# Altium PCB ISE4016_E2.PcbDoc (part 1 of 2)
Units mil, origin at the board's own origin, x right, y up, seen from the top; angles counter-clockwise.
Board outline 5600 x 2000 mil, 4 copper layers (Top Layer, InternalPlane1, MidLayer2, Bottom Layer), stack 59 mil thick; 110 components, 63 nets, 365 pads, 250 vias.
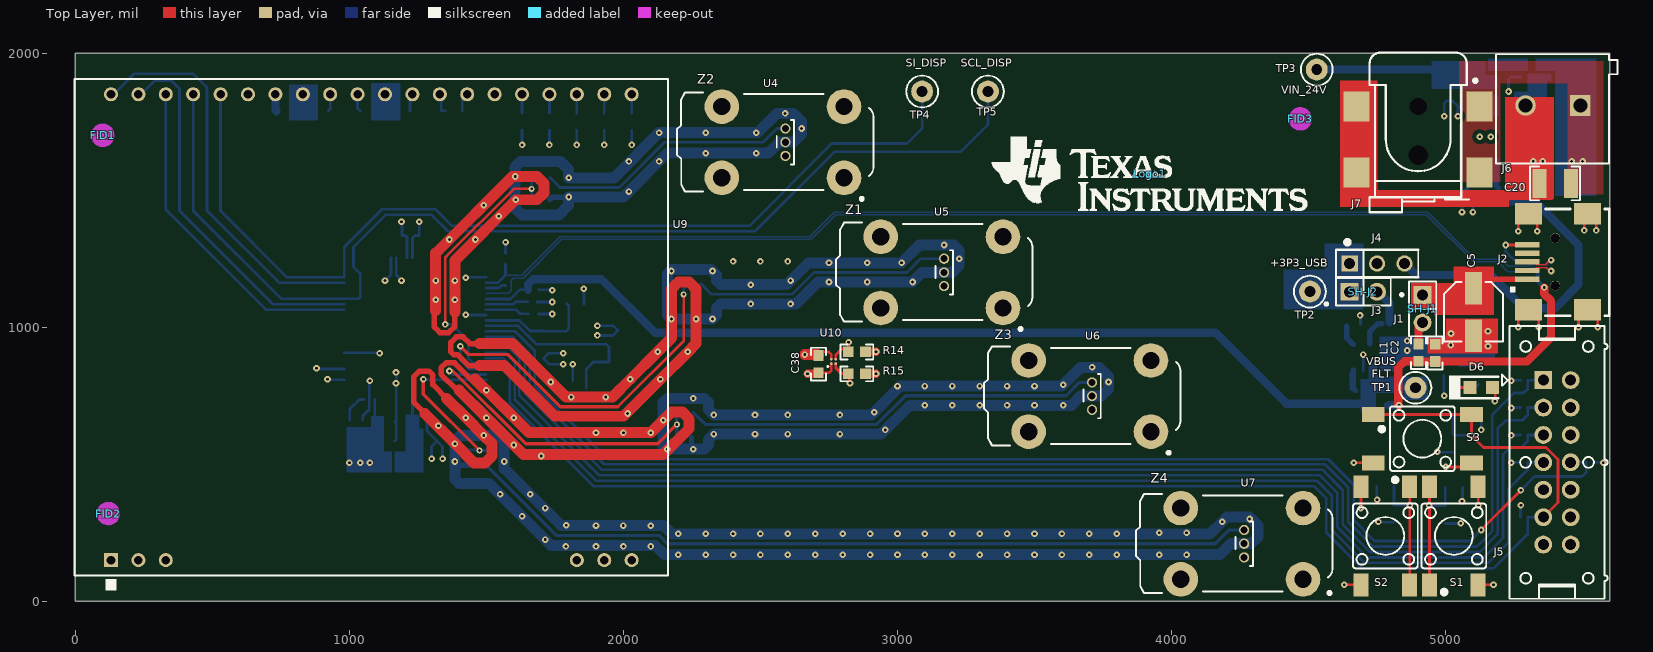
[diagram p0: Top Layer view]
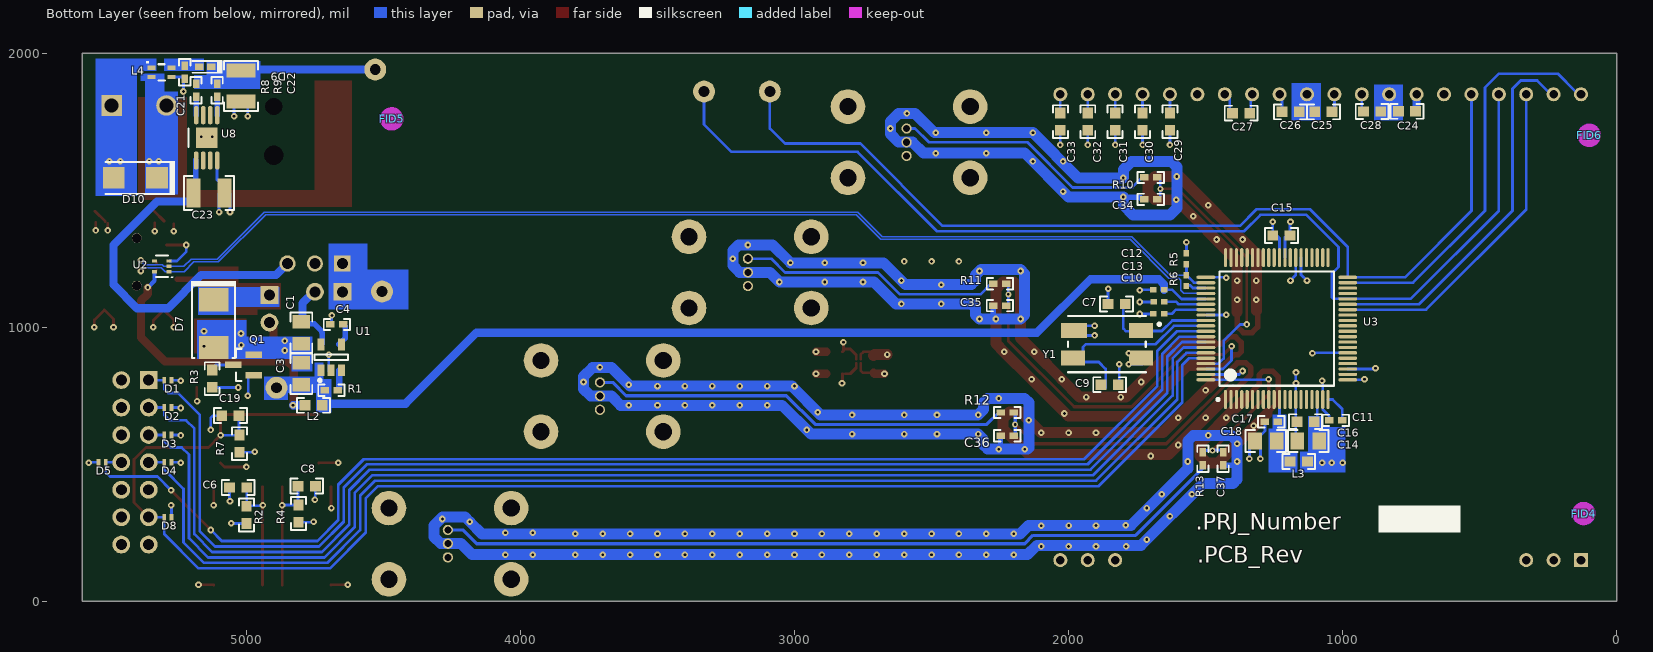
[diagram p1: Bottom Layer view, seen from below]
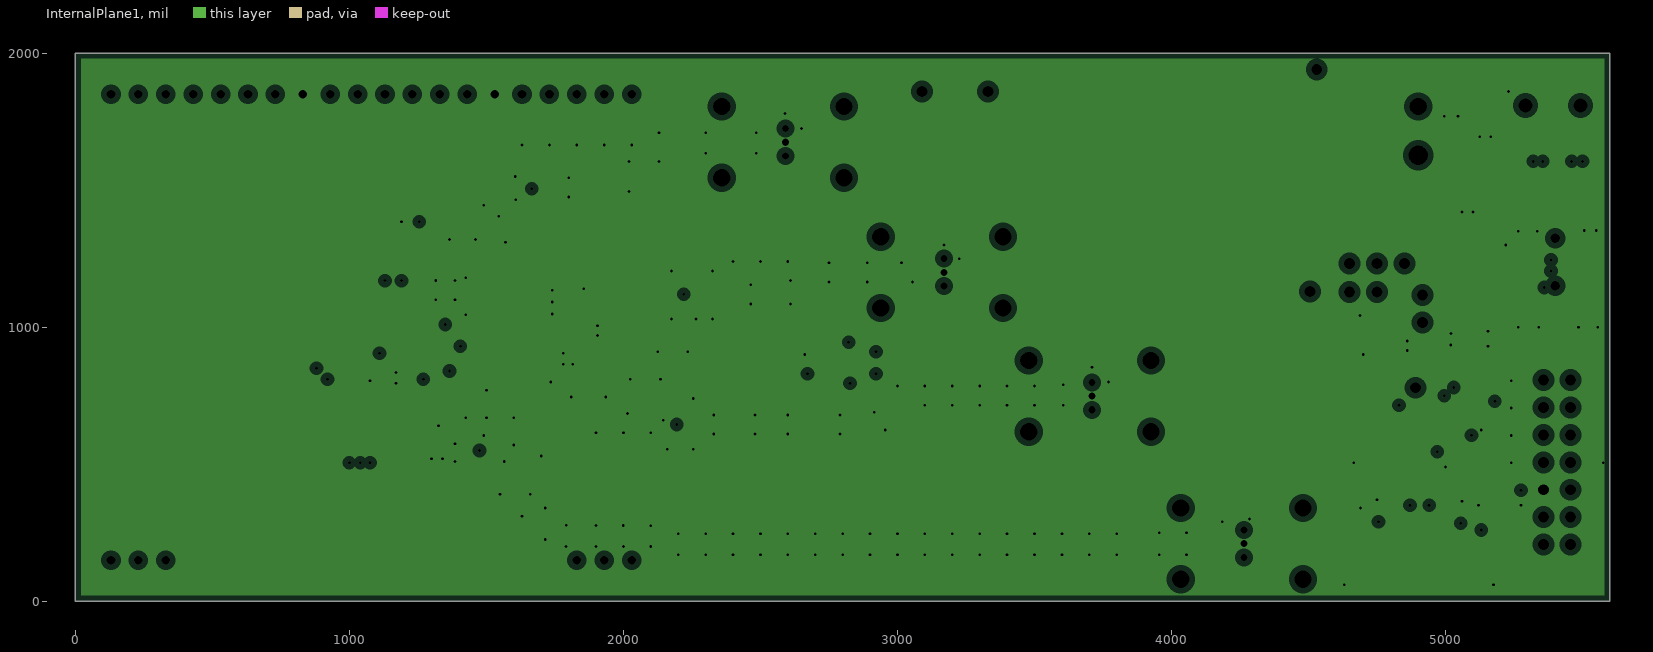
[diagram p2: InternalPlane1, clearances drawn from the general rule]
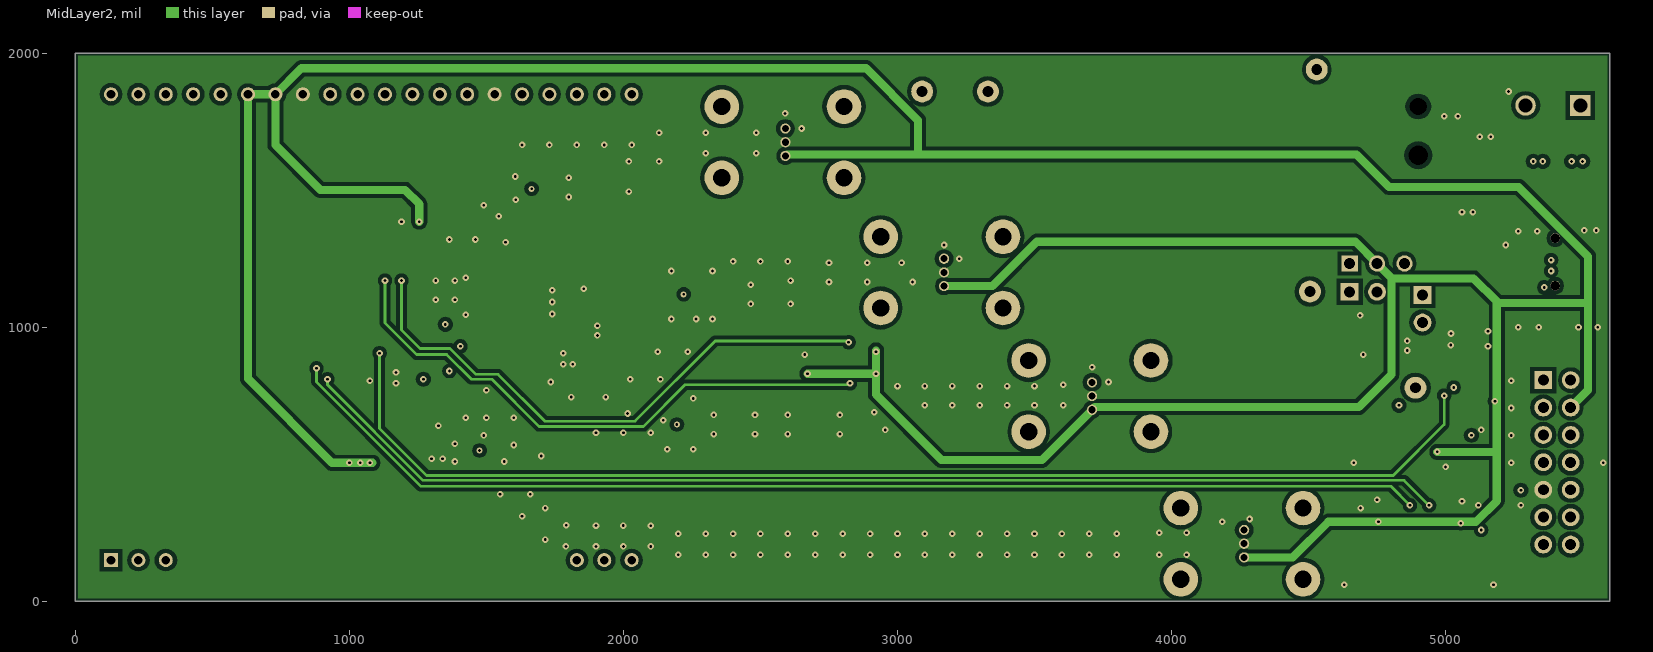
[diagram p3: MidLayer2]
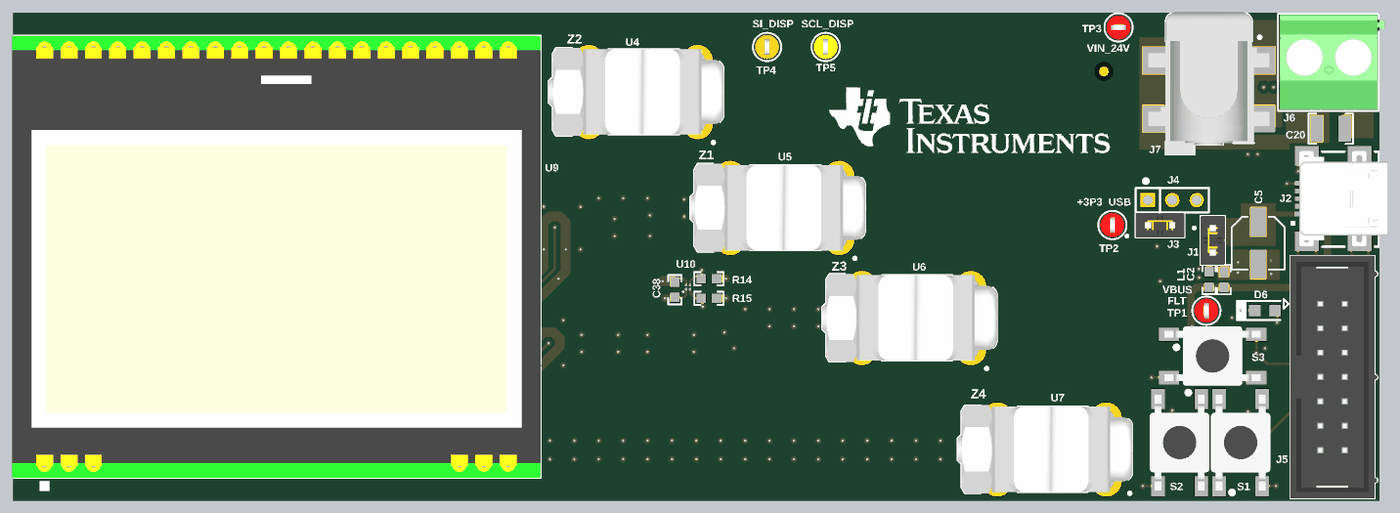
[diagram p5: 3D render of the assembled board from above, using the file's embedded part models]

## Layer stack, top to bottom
Top Layer: signal copper 1.4
Dielectric: prepreg 5.2, 370 HR, Dk 4.8
InternalPlane1: plane copper 1.4, net GND
Dielectric: core 43, 370 HR, Dk 4.8
MidLayer2: signal copper 1.4
Dielectric: prepreg 5.2, 370 HR, Dk 4.8
Bottom Layer: signal copper 1.4

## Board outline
0,0 5600,0 5600,2000 0,2000

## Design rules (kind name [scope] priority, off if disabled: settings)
AcuteAngle [All] p1: minimum=4.50000000000000E+0001 checktracksonly=FALSE
AssemblyTestPointUsage [All] p1: valid=2
Clearance Clearance_BoardEdge_MountingHoles [OnCopper and InComponentClass('Mounting Holes') vs IsKeepOut] p1: gap=40
Clearance Clearance_BoardEdge_Poly [OnCopper and InPoly vs IsKeepOut] p2: gap=25
Clearance Clearance_BoardEdge [OnCopper and Not InComponentClass('Logo') and not InComponentClass('FiducialMark') and not InRegion(1000,500,4000,800) and Not IsKeepout vs IsKeepOut] p3: gap=75
Clearance Clearance_Poly [InPolygon] p4: gap=15
Clearance [All] p5: gap=5
ComponentClearance ComponentClearance_Logo [InComponentClass('Logo')] p1 off: gap=50 collisioncheckmode=3 verticalgap=10 showdistances=FALSE
ComponentClearance ComponentClearance_ScrewToNut [(HasFootprint('NY PMS 440 0025 PH')) vs (HasFootprint('Keystone_1902C'))] p2: gap=5 collisioncheckmode=3 verticalgap=10 showdistances=FALSE
ComponentClearance ComponentClearance_MountingHoles [InComponentClass('Mounting Holes')] p3 off: gap=250 collisioncheckmode=3 verticalgap=100000 showdistances=FALSE
ComponentClearance ComponentClearance_SmallPassives [HasFootprint('0201*') or HasFootprint('0402*') or HasFootprint('0508') or HasFootprint('0603*') or HasFootprint('0612') or HasFootprint('0805*') or HasFootprint('0815*') or HasFootprint('0830*') or HasFootprint('1206*') or HasFootprint('1210*') or HasFootprint('1808*') or HasFootprint('1812*') or HasFootprint('1825*') or HasFootprint('2010*') or HasFootprint('2220*') or HasFootprint('2225*') or HasFootprint('2512*') or HasFootprint('2728*') or HasFootprint('3518*') vs HasFootprint('0201*') or HasFootprint('0402*') or HasFootprint('0508') or HasFootprint('0603*') or HasFootprint('0612') or HasFootprint('0805*') or HasFootprint('0815*') or HasFootprint('0830*') or HasFootprint('1206*') or HasFootprint('1210*') or HasFootprint('1808*') or HasFootprint('1812*') or HasFootprint('1825*') or HasFootprint('2010*') or HasFootprint('2220*') or HasFootprint('2225*') or HasFootprint('2512*') or HasFootprint('2728*') or HasFootprint('3518*')] p4: gap=20 collisioncheckmode=3 verticalgap=10 showdistances=FALSE
ComponentClearance ComponentClearance_THtoSMT [IsThruComponent vs IsSMTComponent] p5 off: gap=100 collisioncheckmode=3 verticalgap=30 showdistances=FALSE
ComponentClearance ComponentClearance_THtoTH [IsThruComponent vs IsThruComponent] p6 off: gap=118.11 collisioncheckmode=3 verticalgap=30 showdistances=FALSE
ComponentClearance [All] p7 off: gap=10 collisioncheckmode=3 verticalgap=10 showdistances=FALSE
DiffPairsRouting [All] p1: maxlimit=100 minlimit=5 mostfreqgap=5 maxuncoupledlength=4000
FabricationTestPointUsage TestPointUsage [All] p1: valid=2 allowmultiple=FALSE
FabricationTestpoint Testpoint [All] p1: side=3 testpointundercomponent=TRUE minsize=40 maxsize=100 preferedsize=60 minholesize=0 maxholesize=40 preferedholesize=32 testpointgrid=1 allowsidetop=TRUE allowsidebottom=TRUE usegrid=TRUE gridtolerance=0.01
FanoutControl Fanout_LCC [IsLCC] p1: bgadir=Out bgaviamode=Centered fanoutstyle=Auto fanoutdirection=Alternating viagrid=1 // Fanout_LCC (Default Rule)
FanoutControl Fanout_BGA [IsBGA] p2: bgadir=Out bgaviamode=Centered fanoutstyle=Auto fanoutdirection=Alternating viagrid=1 // Fanout_BGA (Default Rule)
FanoutControl Fanout_Default [All] p4: bgadir=Out bgaviamode=Centered fanoutstyle=Auto fanoutdirection=Alternating viagrid=1 // Fanout_Default (Default Rule)
FanoutControl Fanout_Small [(CompPinCount < 5)] p5: bgadir=Out bgaviamode=Centered fanoutstyle=Auto fanoutdirection=OutThenIn viagrid=1 // Fanout_Small (Default Rule)
Height [All] p1: minheight=0 maxheight=4000 prefheight=500
HoleSize [All] p1: absolutevalues=TRUE maxlimit=251 minlimit=8 maxpercent=80.000 minpercent=20.000
MinimumAnnularRing [All] p1: minimumring=5
MinimumSolderMaskSliver MinimumSolderMaskSliver_Logo [InComponentClass('Logo') vs InComponentClass('Logo')] p1: minsoldermaskwidth=0.7
MinimumSolderMaskSliver [All] p2: minsoldermaskwidth=1
PlaneClearance [All] p1: clearance=20
PlaneConnect [All] p1: planeconnectstyle=Relief reliefexpansion=10 reliefentries=4 reliefconductorwidth=10 reliefairgap=10
PolygonConnect [All] p1: connectstyle=Direct reliefconductorwidth=10 reliefentries=4 polygonreliefangle="90 Angle" airgapwidth=10
RoutingVias [All] p1: holewidth=16 width=34 viastyle="Through Hole" minholewidth=8 minwidth=20 maxholewidth=40 maxwidth=65
SMDToCorner [All] p1: distance=30000
SilkToSilkClearance [All] p1: silktosilkclearance=5
SilkscreenOverComponentPads [All] p1: minsilkscreentomaskgap=5
SolderMaskExpansion [All] p1: expansion=3
Width "Schematic Width Constraint_6" [InNet('NetC20_1')] p1: maxlimit=80 minlimit=80 preferedwidth=80
Width "Schematic Width Constraint_5" [InNet('+3P3_USB')] p2: maxlimit=100 minlimit=5 preferedwidth=25
Width "Schematic Width Constraint_4" [InNet('VBUS_FLT')] p3: maxlimit=100 minlimit=5 preferedwidth=25
Width "Schematic Width Constraint_3" [InNet('+3P3V_OUT')] p4: maxlimit=100 minlimit=5 preferedwidth=25
Width "Schematic Width Constraint_2" [InNet('VBUS')] p5: maxlimit=100 minlimit=5 preferedwidth=25
Width "Schematic Width Constraint_1" [InNet('NetC5_1')] p6: maxlimit=100 minlimit=5 preferedwidth=25
Width "Schematic Width Constraint" [InNet('NetC21_1')] p7: maxlimit=20 minlimit=20 preferedwidth=20
Width [All] p8: maxlimit=100 minlimit=5 preferedwidth=10 minimp=50.000000 maximp=50.000000 favimp=50.000000 checkconnectedcopper=TRUE
12 further rules are at their usual default settings.

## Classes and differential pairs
component class Shunt: SH-J1 SH-J2
component class Power: C20 C21 C22 C23 C24 C25 C26 C27 C28 C29 C30 C31 C32 C33 C38 D9 D10 J6 J7 L4 R8 R9 R14 R15 TP3 TP4 TP5 U8 U9 U10
component class "Analog and EP": C1 C2 C3 C4 C5 C6 C7 C8 C9 C10 C11 C12 C13 C14 C15 C16 C17 C18 C19 C34 C35 C36 C37 D1 D2 D3 D4 D5 D6 D7 D8 J1 J2 J3 J4 J5 L1 L2 L3 Q1 R1 R2 R3 R4 R5 R6 R7 R10 R11 R12 R13 S1 S2 S3 SH-J1 SH-J2 TP1 TP2 U1 U2 U3 U4 U5 U6 U7 Y1 Z1 Z2 Z3 Z4
component class Logo: Logo1
component class Hardware_ANSI-B: FID1 FID2 FID3 FID4 FID5 FID6 Logo1 ZZ2 ZZ3 ZZ4
component class FiducialMark: FID1 FID2 FID3 FID4 FID5 FID6
component class AssemblyNote: ZZ2 ZZ3 ZZ4
differential pair USB_D: +USB_D_P -USB_D_N

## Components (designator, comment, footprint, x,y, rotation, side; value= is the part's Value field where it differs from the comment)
C1 "0805ZD475KAT2A" 0805_HV 4800,980 r270 bottom
C2 "C1608X7R1C105K" 0603 4962,906 r90 top
C3 "C0805C225K8PACTU" 0805_HV 4800,830 r90 bottom
C4 "GRM155R71C103KA01D" 0402 4670,1010 r0 bottom
C5 "EEE-1AA220WR" CAPSMT_62_E55 5102,1056 r270 top
C6 "06031C222JAT2A" 0603 5030,415 r0 bottom
C7 "06035A180JAT2A" 0603 1825,1085 r0 bottom
C8 "06031C222JAT2A" 0603 4780,420 r180 bottom
C9 "06035A180JAT2A" 0603 1850,790 r180 bottom
C10 "GRM155R61A224KE19D" 0402L 1671,1049 r0 bottom
C11 "GRM155R61A474KE15D" 0402 1025,660 r0 bottom
C12 "GRM155R61A224KE19D" 0402L 1671,1137 r0 bottom
C13 "GRM155R61A224KE19D" 0402L 1670,1093 r0 bottom
C14 "C0805C106K8PACTU" 0805_HV 1125,585 r0 bottom
C15 "06033C104JAT2A" 0603 1223.03,1334.4 r180 bottom
C16 "06033C104JAT2A" 0603 1135,655 r0 bottom
C17 "GRM155R61C104KA88D" 0402 1260,655 r0 bottom
C18 "C0805C106K8PACTU" 0805_HV 1280,585 r0 bottom
C19 "06031C222JAT2A" 0603 5058.33,677.27 r0 bottom
C20 "C1210C102KGRACTU" 1210 5400,1525 r180 top
C21 "GCM155R71H103KA55D" 0402 5225,1930 r270 bottom
C22 "GRM32ER71H106KA12L" 1210 5020,1880 r270 bottom
C23 "GRM32ER71H106KA12L" 1210 5136.7,1489.5 r180 bottom
C24 "C1608X7R1C105K" 0603 765,1788 r0 bottom
C25 "C1608X7R1C105K" 0603 1070,1786 r0 bottom
C26 "C1608X7R1C105K" 0603 1190,1786 r0 bottom
C27 "C1608X7R1C105K" 0603 1370,1781 r0 bottom
C28 "C1608X7R1C105K" 0603 892,1787 r180 bottom
C29 "C1608X7R1C105K" 0603 1630,1750 r270 bottom
C30 "C1608X7R1C105K" 0603 1730,1750 r270 bottom
C31 "C1608X7R1C105K" 0603 1830,1750 r270 bottom
C32 "C1608X7R1C105K" 0603 1930,1750 r270 bottom
C33 "C1608X7R1C105K" 0603 2030,1750 r270 bottom
C34 "GRM155R61A474KE15D" 0402 1700,1466.3 r0 bottom
C35 "GRM155R61A474KE15D" 0402 2250.55,1078.7 r0 bottom
C36 "GRM155R61A474KE15D" 0402 2223.35,603.7 r0 bottom
C37 "GRM155R61A474KE15D" 0402 1436,520 r270 bottom
C38 "06033C104JAT2A" 0603 2711.65,865 r90 top
D1 "TPD1E10B06DPYR" DPY0002A_N 5286.69,806.81 r180 bottom
D2 "TPD1E10B06DPYR" DPY0002A_N 5286.69,706.81 r180 bottom
D3 "TPD1E10B06DPYR" DPY0002A_N 5286.69,606.81 r180 bottom
D4 "TPD1E10B06DPYR" DPY0002A_N 5286.69,506.81 r180 bottom
D5 "TPD1E10B06DPYR" DPY0002A_N 5526.69,506.81 r0 bottom
D6 "LTST-C190GKT" LED_LTST-C171 5130,780 r180 top
D7 "1SMB5922BT3G" SMB 5120,1012.73 r270 bottom
D8 "TPD1E10B06DPYR" DPY0002A_N 5286.69,306.81 r180 bottom
D9 "NSR0240V2T1G" SOD-523 5150,1950 r0 bottom
D10 "SMAJ36CA" SMA 5405,1545 r0 bottom
FID1 "Fiducial" Fiducial10-20#1 100,1700 r0 top
FID2 "Fiducial" Fiducial10-20#1 120,320 r0 top
FID3 "Fiducial" Fiducial10-20#1 4470,1760 r0 top
FID4 "Fiducial" Fiducial10-20#2 120,320 r180 bottom
FID5 "Fiducial" Fiducial10-20#2 4470,1760 r180 bottom
FID6 "Fiducial" Fiducial10-20#2 100,1700 r180 bottom
J1 "90120-0122" CONN_90120-0122 4916,1067 r270 top
J2 "1734035-2" CONN_USB-Mini-B-1734035-2 5400.31,1238.19 r90 top
J3 "90120-0122" CONN_90120-0122 4700,1129 r0 top
J4 "PEC03SAAN" CONN_PEC03SAAN 4750.22,1232.27 r0 top
J5 "SBH11-PBPC-D07-ST-BK" CONN_SBH11-PBPC-D07-ST-BK 5406.69,506.81 r270 top
J6 "1715721" PhoenixContact_1715721 5392,1809 r180 top
J7 "PJ-002AH-SMT-TR" CUI_PJ-002AH-SMT 4900,1685 r270 top
L1 "BLM18SG331TN1D" 0603 4901,907 r270 top
L2 "BLM18SG331TN1D" 0603 4755,715 r180 bottom
L3 "BLM18SG331TN1D" 0603 1160,510 r0 bottom
L4 "SRF2012-361YA" SRF2012A 5310,1930 r180 bottom
Logo1 "Texas Instruments" TI_Stacked_Overlay_Medium 3920,1560 r0 top
Q1 "BSS138" SOT-23 5010.53,862.27 r0 bottom
R1 "CRCW04020000Z0ED" 0402 4690,770 r0 bottom
R2 "CRCW060347K5FKEA" 0603 5000,315 r270 bottom
R3 "CRCW0603200RJNEA" 0603 5125,812 r270 bottom
R4 "CRCW060347K5FKEA" 0603 4810,320 r270 bottom
R5 "CRCW04021M00FKED" 0402L 1570,1250 r90 bottom
R6 "CRCW04021K50FKED" 0402L 1570,1170 r90 bottom
R7 "CRCW060347K5FKEA" 0603 5025,575 r270 bottom
R8 "ERJ-2GE0R00X" 0402 5184,1865 r270 bottom
R9 "ERJ-2GE0R00X" 0402 5107,1865 r270 bottom
R10 "CRCW04021K50FKED" 0402 1700,1546.3 r180 bottom
R11 "CRCW04021K50FKED" 0402 2250.55,1158.7 r180 bottom
R12 "CRCW04021K50FKED" 0402 2223.35,688.7 r180 bottom
R13 "CRCW04021K50FKED" 0402 1510,520 r90 bottom
R14 "CRCW06033K16FKEA" 0603 2851.65,910 r0 top
R15 "CRCW06033K16FKEA" 0603 2851.65,830 r0 top
S1 "4-1437565-1" SW_FSM4JSMA 5030.31,238.19 r180 top
S2 "4-1437565-1" SW_FSM4JSMA 4780.31,238.19 r0 top
S3 "4-1437565-1" SW_FSM4JSMA 4915.31,593.19 r90 top
SH-J1 "2SN-BK-G" 2SN-BK-G 4916,1067 r90 top
SH-J2 "2SN-BK-G" 2SN-BK-G 4700,1129 r0 top
TP1 "5000" Keystone5000 4890,779 r0 top
TP2 "5000" Keystone5000 4505,1130 r0 top
TP3 "5000" Keystone5000 4530,1940 r90 top
TP4 "5003" Keystone5003 3090,1860 r0 top
TP5 "5004" Keystone5004 3330,1860 r0 top
U1 "LP2985AIM5-3.3/NOPB" MF05A_N 4691,890 r90 bottom
U2 "TPD3E001DRLR" DRL0005A 5309,1222 r0 bottom
U3 "MSP430F5529IPN" PN0080A_N 1240,995 r90 bottom
U4 "DRV5053VAQLPGRQ1" LPG0003A 2591,1675 r90 top
U5 "DRV5053VAQLPGRQ1" LPG0003A 3170,1200 r90 top
U6 "DRV5053VAQLPGRQ1" LPG0003A 3710,748.54 r90 top
U7 "DRV5053VAQLPGRQ1" LPG0003A 4265,210 r90 top
U8 "TPS7A1633QDGNRQ1" DGN0008C_N 5145,1691 r90 bottom
U9 "EA DOGM128W-6" "LCD-MODULE_EA DOGM128W-6" 1080,1000 r0 top locked
U10 "TMP103AYFF" YFF0004AAAA 2766.65,875 r90 top
Y1 "ABMM-24.000MHZ-B2-T" Abracon_ABMM 1860,938 r270 bottom
Z1 "TI Flux Concentrator Clip" "TI Flux Concentrator Clip" 3170,1200 r180 top
Z2 "TI Flux Concentrator Clip" "TI Flux Concentrator Clip" 2590,1675 r180 top
Z3 "TI Flux Concentrator Clip" "TI Flux Concentrator Clip" 3710,748.54 r180 top
Z4 "TI Flux Concentrator Clip" "TI Flux Concentrator Clip" 4265,210 r180 top
ZZ2 "These assemblies are ESD sensitive, ESD precautions shall be observed." AssemblyNote 185,3829.11 r0 top
ZZ3 "These assemblies must be clean and free from flux and all contaminants. Use of no clean flux is not acceptable." AssemblyNote 185,3740.56 r0 top
ZZ4 "These assemblies must comply with workmanship standards IPC-A-610 Class 2, unless otherwise specified." AssemblyNote 185,3652 r0 top

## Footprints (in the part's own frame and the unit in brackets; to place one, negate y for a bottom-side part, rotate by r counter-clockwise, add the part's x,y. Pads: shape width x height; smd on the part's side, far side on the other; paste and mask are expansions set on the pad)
2SN-BK-G [mil] "Samtec STEP model"
  round 1 on Mech3: 0(0,0)
  body extent -78,-39 79,39, height 188
0402 [mm] "0402 from SM-752 data"
  rect 0.8x0.6 smd: 1(-0.6,0) 2(0.6,0)
  silkscreen extent -1.22,-0.52 1.22,0.52, body extent -0.55,-0.3 0.55,0.3, height 0.6
0402L [mm] "0402 from SM-752 data"
  rect 0.6x0.5 smd: 1(-0.5,0) 2(0.5,0)
  body extent -0.55,-0.3 0.55,0.3, height 0.6
0603 [mm] "0603 from SM-752 data"
  rect 1x0.95 smd: 1(-0.8,0) 2(0.8,0)
  silkscreen extent -1.52,-0.69 1.52,0.69, body extent -0.87,-0.47 0.87,0.47, height 0.85
0805_HV [mil] "0805 with 30mil clearance between pads"
  rect 50x63 smd: 1(-40,0) 2(40,0)
  silkscreen extent -74,-40 74,40, body extent -43,-29 43,29, height 43
1210 [mm] "1210 from SM-752 data"
  rect 1.3x2.7 smd: 1(-1.45,0) 2(1.45,0)
  silkscreen extent -2.32,-1.57 2.32,1.57, body extent -1.7,-1.35 1.7,1.35, height 1.35
Abracon_ABMM [mm] "Abracon"
  rect 1.4x2.2 smd: 1(-1.27,3.15) 2(1.27,3.15) 3(1.27,-3.15)
  rect 1.4x2.4 smd: 4(-1.27,-3.05)
  silkscreen extent -2.6,-3.6 2.6,4.98, body extent -2.6,-3.6 2.6,3.6, height 1.3
AssemblyNote [mil] "Assembly Note"
CAPSMT_62_E55 [mm] "5 x 5.2mm:  Chemi-Con E55"
  rect 3x1.6 smd: 1(-2.2,0) 2(2.2,0)
  silkscreen extent -2.75,-2.75 2.75,2.75, body extent -2.76,-2.76 2.76,2.76, height 5.5
CONN_90120-0122 [mm] "Molex"
  rect 1.65x1.65 hole 1.016 mask+0: 1(-1.27,0)
  round 1.65 hole 1.016 mask+0: 2(1.27,0)
  silkscreen extent -2.54,-2.05 2.54,1.27, body extent -2.54,-1.27 2.54,1.27, height 9.29
CONN_PEC03SAAN [mm] "SULLINS"
  rect 1.5x1.5 hole 1.016: 1(-2.54,0)
  round 1.5 hole 1.016: 2(0,0) 3(2.54,0)
  silkscreen extent -3.81,-1.27 3.81,2.18, body extent -3.84,-1.3 3.84,1.3, height 8.38
CONN_SBH11-PBPC-D07-ST-BK [mm] "Sullins recommended land pattern"
  rect 1.65x1.65 hole 1.016 mask+0: 1(-7.62,-1.27)
  round 1.65 hole 1.016 mask+0: 2(-7.62,1.27) 3(-5.08,-1.27) 4(-5.08,1.27) 5(-2.54,-1.27) 6(-2.54,1.27) 7(0,-1.27) 8(0,1.27) 9(2.54,-1.27) 10(2.54,1.27) 11(5.08,-1.27) 12(5.08,1.27) 13(7.62,-1.27) 14(7.62,1.27)
  silkscreen extent -12.64,-5.08 12.64,4.7, body extent -12.64,-4.4 12.64,4.7, height 9.12
CONN_USB-Mini-B-1734035-2 [mm] "Tyco Connectivity recommended land pattern"
  rect 0.5x2.3 smd: 1(-1.6,2.6) 2(-0.8,2.6) 3(0,2.6) 4(0.8,2.6) 5(1.6,2.6)
  rect 2x2.5 smd: 6(4.45,2.5) 7(4.45,-3) 8(-4.45,-3) 9(-4.45,2.5)
  round 0.9 hole 0.9 unplated: 10(2.2,0) 11(-2.2,0)
  silkscreen extent -5,-5 4.9,4.19, body extent -4.95,-5.9 4.95,3.3, height 4.1
CUI_PJ-002AH-SMT [mm] "CUI"
  rect 2.8x2.4 smd: 1(-3.05,5.7) 1A(3.05,5.7) 2(-3.05,-5.7) 3(3.05,-5.7)
  round 1 hole 1.6 unplated: MH1(-3.05,0)
  round 1.524 hole 1.8 unplated: MH2(1.45,0)
  silkscreen extent -8.05,-4.5 6.75,5.45, body extent -8.05,-6.3 6.75,6.3, height 11.2
DGN0008C_N [mm] "TSOP, 8-Leads, Body 3x3mm, Pitch 0.65mm, Thermal Pad 1.98x1.88mm, IPC Medium Density"
  oval 1.7x0.45 smd mask+0.05: 1(-2.1,0.975) 2(-2.1,0.325) 3(-2.1,-0.325) 4(-2.1,-0.975) 5(2.1,-0.975) 6(2.1,-0.325) 7(2.1,0.325) 8(2.1,0.975)
  rect 1.88x1.98 smd mask+0.07: 9(0,0)
  silkscreen extent -0.85,1.68 0.85,1.68, body extent -2.45,-1.5 2.45,1.5, height 0.94
DPY0002A_N [mm] "DFN, 2-Leads, Body 1.0x0.6x0.4mm, IPC Medium Density"
  rect 0.35x0.62 smd: 1(-0.34,0) 2(0.34,0)
  body extent -0.5,-0.3 0.5,0.3, height 0.4
DRL0005A [mm] "SOTFL, 5-Flat Leads, Body 1.2x1.6x0.6mm, Pitch 0.5mm, TI Recommended"
  rect 0.45x0.3 smd: 1(-0.675,0.5) 2(-0.675,0) 3(-0.675,-0.5) 4(0.675,-0.5) 5(0.675,0.5)
  silkscreen extent -1,-1 0.55,1.05, body extent -0.65,-0.85 0.65,0.85, height 0.6
Fiducial10-20#1 [mm]
  round 1 smd paste-0.5 mask+0.5: 1(0,0)
  Top Layer keep-out circle w1.178: c0,0 r0.5
Fiducial10-20#2 [mm]
  round 1 smd mask+0.5: 1(0,0)
  Top Layer keep-out circle w1.178: c0,0 r0.5
Keystone5000 [mil] "For Keystone 500x miniature loop terminals"
  round 80 hole 40: 1(0,0)
  silkscreen extent -58,-58 58,58, body extent -49,-49 49,49, height 182
Keystone5003 [mil] "For Keystone 500x miniature loop terminals"
  round 80 hole 40: 1(0,0)
  silkscreen extent -58,-58 58,58, body extent -49,-49 49,49, height 182
Keystone5004 [mil] "For Keystone 500x miniature loop terminals"
  round 80 hole 40: 1(0,0)
  silkscreen extent -58,-58 58,58, body extent -49,-49 49,49, height 182
"LCD-MODULE_EA DOGM128W-6" [mm] "LCD-MODULE"
  rect 1.3x1.3 hole 0.8: 1(-24.13,-21.59)
  round 1.3 hole 0.8: 2(-21.59,-21.59) 3(-19.05,-21.59) 18(19.05,-21.59) 19(21.59,-21.59) 20(24.13,-21.59) 21(24.13,21.59) 22(21.59,21.59) 23(19.05,21.59) 24(16.51,21.59) 25(13.97,21.59) 26(11.43,21.59) 27(8.89,21.59) 28(6.35,21.59) 29(3.81,21.59) 30(1.27,21.59) 31(-1.27,21.59) 32(-3.81,21.59) 33(-6.35,21.59) 34(-8.89,21.59) 35(-11.43,21.59) 36(-13.97,21.59) 37(-16.51,21.59) 38(-19.05,21.59) 39(-21.59,21.59) 40(-24.13,21.59)
  silkscreen extent -27.5,-24.38 27.5,23, body extent -27.5,-23 27.5,23, height 7.31
LED_LTST-C171 [mm] "LITE-ON"
  rect 1.2x1.2 smd: 1(-1.05,0) 2(1.05,0)
  silkscreen extent -1.6,-1.1 3,1.1, body extent -1.05,-0.67 1.05,0.67, height 0.8
LPG0003A [mm] "TO, Flat Index; 3 In-Line, Axial Leads Texas Instruments Recommended"
  round 0.95 hole 0.66: 1(-1.27,0) 2(0,0) 3(1.27,0)
  silkscreen extent -2.05,-0.81 2.05,0.8, body extent -2.05,-0.81 2.05,0.8, height 5.5
MF05A_N [mm] "SOT23, 5-Leads, Body 2.9x1.6mm, Pitch 0.95mm, Lead Span 2.8mm, IPC Medium Density"
  rect 1.1x0.65 smd: 1(-1.2,0.95) 2(-1.2,0) 3(-1.2,-0.95) 4(1.2,-0.95) 5(1.2,0.95)
  silkscreen extent -2.26,-1.55 0.25,1.55, body extent -0.9,-1.55 0.9,1.55, height 1.19
PhoenixContact_1715721 [mm] "Phoenix Contact 1715721 used on LM3445 design from Longmont"
  rect 1.905x1.905 hole 1.3: 1(-2.54,0)
  round 1.9 hole 1.3: 2(2.54,0)
  silkscreen extent -5.97,-4.75 5.28,5.36, body extent -5.82,-4.6 5.08,5.2, height 14.2
PN0080A_N [mm] "QFP, 80-Leads, Body 12x12mm, Pitch 0.5mm, IPC Medium Density"
  oval 1.75x0.3 smd: 1(-6.575,4.75) 2(-6.575,4.25) 3(-6.575,3.75) 4(-6.575,3.25) 5(-6.575,2.75) 6(-6.575,2.25) 7(-6.575,1.75) 8(-6.575,1.25) 9(-6.575,0.75) 10(-6.575,0.25) 11(-6.575,-0.25) 12(-6.575,-0.75) 13(-6.575,-1.25) 14(-6.575,-1.75) 15(-6.575,-2.25) 16(-6.575,-2.75) 17(-6.575,-3.25) 18(-6.575,-3.75) 19(-6.575,-4.25) 20(-6.575,-4.75) 41(6.575,-4.75) 42(6.575,-4.25) 43(6.575,-3.75) 44(6.575,-3.25) 45(6.575,-2.75) 46(6.575,-2.25) 47(6.575,-1.75) 48(6.575,-1.25) 49(6.575,-0.75) 50(6.575,-0.25) 51(6.575,0.25) 52(6.575,0.75) 53(6.575,1.25) 54(6.575,1.75) 55(6.575,2.25) 56(6.575,2.75) 57(6.575,3.25) 58(6.575,3.75) 59(6.575,4.25) 60(6.575,4.75)
  oval 0.3x1.75 smd: 21(-4.75,-6.575) 22(-4.25,-6.575) 23(-3.75,-6.575) 24(-3.25,-6.575) 25(-2.75,-6.575) 26(-2.25,-6.575) 27(-1.75,-6.575) 28(-1.25,-6.575) 29(-0.75,-6.575) 30(-0.25,-6.575) 31(0.25,-6.575) 32(0.75,-6.575) 33(1.25,-6.575) 34(1.75,-6.575) 35(2.25,-6.575) 36(2.75,-6.575) 37(3.25,-6.575) 38(3.75,-6.575) 39(4.25,-6.575) 40(4.75,-6.575) 61(4.75,6.575) 62(4.25,6.575) 63(3.75,6.575) 64(3.25,6.575) 65(2.75,6.575) 66(2.25,6.575) 67(1.75,6.575) 68(1.25,6.575) 69(0.75,6.575) 70(0.25,6.575) 71(-0.25,6.575) 72(-0.75,6.575) 73(-1.25,6.575) 74(-1.75,6.575) 75(-2.25,6.575) 76(-2.75,6.575) 77(-3.25,6.575) 78(-3.75,6.575) 79(-4.25,6.575) 80(-4.75,6.575)
  silkscreen extent -6.7,-5.3 5.3,5.58, body extent -7,-7 7,7, height 1.52
SMA [mm] "Molded Diode, 2-Leads, Body 4.3x2.6mm, IPC Medium Density, based on OnSemi component dimensions and land pattern"
  rect 2x2 smd: 1(-2,0) 2(2,0)
  silkscreen extent -3.66,-1.57 2.79,1.57, body extent -2.6,-1.3 2.6,1.3, height 2.42
SMB [mil] "Molded Diode, 2-Leads, Body 5.4x3.6mm, IPC Medium Density, based on OnSemi component dimensions"
  rect 85x107.99 smd: 1(-87.01,0) 2(87.01,0)
  silkscreen extent -155,-82 125,82, body extent -106,-71 106,71, height 91
SOD-523 [mm] "NXP Semiconductor recommended land pattern, nominal STEP model"
  rect 0.8x0.6 smd paste-0.05: 1(-0.55,0) 2(0.55,0)
  silkscreen extent -1.6,-0.64 1.2,0.63, body extent -0.8,-0.4 0.8,0.4, height 0.72
SOT-23 [mm] "SOT23, 3-Leads, Body 2.9x1.3mm, Pitch 0.95mm, Lead Span 2.5mm, IPC Medium Density"
  rect 1.5x0.6 smd: 1(-0.95,0.95) 2(-0.95,-0.95) 3(0.95,0)
  silkscreen extent 0.2,-1.5 0.7,1.5, body extent -1.16,-1.45 1.21,1.45, height 1
SRF2012A [mm] "BOURNS"
  rect 0.75x0.4 smd: 1(-0.925,0.425) 2(0.925,0.425) 3(0.925,-0.425) 4(-0.925,-0.425)
  silkscreen extent -1.42,-0.75 0.3,1.05, body extent -1.1,-0.7 1.1,0.7, height 1.41
SW_FSM4JSMA [mm] "Alcoswitch"
  rect 1.4x2.1 smd: 1(2.25,4.55) 2(2.25,-4.55) 3(-2.25,4.55) 4(-2.25,-4.55)
  silkscreen extent -3,-3 3,5.4, body extent -3,-5 3,5, height 5.1
"TI Flux Concentrator Clip" [mm] "TI Flux Concentrator Clip"
  round 3.21 hole 1.6: 1(-5.46,3.3) 2(-5.46,-3.3) 3(5.87,-3.3) 4(5.87,3.3)
  silkscreen extent -8.18,-4.61 10.03,5.35, body extent -8.21,-4.6 10.01,4.56, height 35.07
TI_Stacked_Overlay_Medium [mil]
  silkscreen extent -576,-136 576,134
YFF0004AAAA [mm] "TI DSBGA 0.790x0.790mm"
  round 0.23 smd paste-0.13 mask+0.04: A1(-0.2,0.2) A2(0.2,0.2) B1(-0.2,-0.2) B2(0.2,-0.2)
  silkscreen extent -0.53,0.47 -0.42,0.58, body extent -0.39,-0.39 0.39,0.39, height 0.63

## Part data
C1: "CAP, CERM, 4.7uF, 10V, +/-10%, X5R, 0805"
C2 C24 C25 C26 C27 C28 C29 C30 C31 C32 C33: "CAP, CERM, 1uF, 16V, +/-10%, X7R, 0603"
C3: "CAP, CERM, 2.2uF, 10V, +/-10%, X5R, 0805"
C4: "CAP, CERM, 0.01uF, 16V, +/-10%, X7R, 0402"
C5: library part EMVE100ADA220ME55G, "CAP ALUM 22UF 10V 20% SMD"
C6 C8 C19: "CAP, CERM, 2200pF, 100V, +/-5%, X7R, 0603"
C7 C9: "CAP, CERM, 18pF, 50V, +/-5%, C0G/NP0, 0603"
C10 C12 C13: "CAP, CERM, 0.22uF, 10V, +/-10%, X5R, 0402"
C11 C34 C35 C36 C37: "CAP, CERM, 0.47uF, 10V, +/-10%, X5R, 0402"
C14 C18: "CAP, CERM, 10uF, 10V, +/-10%, X5R, 0805"
C15 C16 C38: "CAP, CERM, 0.1uF, 25V, +/-5%, X7R, 0603"
C17: "CAP, CERM, 0.1uF, 16V, +/-10%, X5R, 0402"
C20: "CAP, CERM, 1000pF, 2000V, +/-10%, X7R, 1210"
C21: "CAP, CERM, 0.01uF, 50V, +/-10%, C0G/NP0, 0402"
C22 C23: "CAP, CERM, 10uF, 50V, +/-10%, X7R, 1210"
D1 D2 D3 D4 D5 D8: "ESD in 0402 Package with 10 pF Capacitance and 6 V Breakdown, 1 Channel, -40 to +125 degC, 2-pin X2SON (DPY), Green (RoHS & no Sb/Br)"
D6: "LED, Green, SMD"
D7: "Diode, Zener, 7.5V, 550mW, SMB"
D9: "Diode, Schottky, 40V, 0.25A, SOD-523"
D10: "Diode, TVS, Bi, 36V, 400W, SMA"
FID1 FID2 FID3 FID4 FID5 FID6: "Fiducial mark.  There is nothing to buy or mount."
J1 J3: "Header, 100mil, 2x1, Tin plated, TH"
J2: "Connector, Receptacle, Mini-USB Type B, R/A, Top Mount SMT"
J4: "Header, 100mil, 3x1, Tin plated, TH"
J5: "Header (shrouded), 100 mil, 7x2, Gold plated, TH"
J6: "Conn Term Block, 2POS, 5.08mm, TH"
J7: "Power Jack, SMT"
L1 L2 L3: "1.5A Ferrite Bead, 330 ohm @ 100MHz, SMD"
L4: "Inductor, Wirewound, Ferrite, , 0.3A, 0.45 ohm, SMD"
Logo1: library part TI_Logo, "Texas Instrument Corporate Signature"
Q1: "MOSFET, N-CH, 50V, 0.22A, SOT-23"
R1 R8 R9: "RES, 0 ohm, 5%, 0.063W, 0402"
R2 R4 R7: "RES, 47.5k ohm, 1%, 0.1W, 0603"
R3: "RES, 200 ohm, 5%, 0.1W, 0603"
R5: "RES, 1.00Meg ohm, 1%, 0.063W, 0402"
R6: "RES, 1.50k ohm, 1%, 0.063W, 0402"
R10 R11 R12 R13: "RES, 1.50 k, 1%, 0.063 W, 0402"
R14 R15: "RES, 3.16k ohm, 1%, 0.1W, 0603"
S1 S2 S3: "Switch, Tactile, SPST-NO, 0.05A, 12V, SMT"
SH-J1 SH-J2: "Shunt, 2mm, Gold plated, Black"
TP1 TP2 TP3: "Test Point, Miniature, Red, TH"
TP4: "Test Point, Miniature, Orange, TH"
TP5: "Test Point, Miniature, Yellow, TH"
U1: "Micropower 150 mA Low-Noise Ultra Low-Dropout Regulator, 5-pin SOT-23, Pb-Free"
U2: "Low-Capacitance + / - 15 kV ESD-Protection Array for High-Speed Data Interfaces, 3 Channels, -40 to +85 degC, 5-pin SOT (DRL), Green (RoHS & no Sb/Br)"
U3: "Mixed Signal MicroController, PN0080A"
U4 U5 U6 U7: "Analog Linear Hall -80 mV/mt-40 - 125°C, LPG0003A"
U8: "60-V, 5-µA IQ, 100-mA, Low-Dropout VOLTAGE REGULATOR With Enable and Power-Good, DGN0008C"
U9: "Module, 128x64-pixel graphics display"
U10: "Low-Power, Digital Temperature Sensor with Two-Wire Interface in WCSP, YFF0004AAAA"
Y1: "Crystal, 24.000MHz, 18pF, SMD"
ZZ2 ZZ3 ZZ4: library part AssemblyNote

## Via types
v1: diameter 24, hole 10, Top Layer to Bottom Layer, tented both sides, 246 vias
v2: diameter 22, hole 10, Top Layer to Bottom Layer, tented both sides, 4 vias

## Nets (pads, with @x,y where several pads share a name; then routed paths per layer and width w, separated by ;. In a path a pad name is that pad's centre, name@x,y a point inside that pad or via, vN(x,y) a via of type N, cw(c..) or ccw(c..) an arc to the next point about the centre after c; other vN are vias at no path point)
3P3_EXT: C23.1 J4.3 U8.1 | length 1351.7
  Bottom Layer w20: U8.1@5184.41,1610.51 5184.41,1516.89 C23.1@5193.11,1508.19
  Bottom Layer w30: J4.3@4850.22,1232.27 4892.49,1190 5165,1190 5286.1,1068.9 5398.9,1068.9 5485,1155 5485,1300 5326.4,1458.6 C23.1@5188,1458.6
+3P3_USB: J3.1 J4.1 TP2.1
+3P3V: C14.1 C15.1 C16.1 C24.1 C38.1 D6.1 J4.2 J5.4 L3.1 R2.2 R4.2 R7.2 R14.2 R15.2 U3.18 U3.50 U4.1 U5.1 U6.1 U7.1 U9.34 U9.35 U10.A1 | length 16861.4
  Top Layer w10: C38.1@2711.65,833.5 2750.16,833.5 2758.65,842 U10.A1@2758.65,867.13 ; v1(5180,730) 5181.34,731.34 D6.1@5181.34,780
  Top Layer w30: v1(2671.65,830) 2708.15,830 C38.1@2711.65,833.5 ; R15.2@2883.15,830 v1(2921.65,830) ; R14.2@2883.15,910 v1(2921.65,910)
  MidLayer2 w30: v1@1084,505 937,505 630,812 U9.35@630,1850 U9.34@730,1850 ; v1(1255,1385) 1255,1449 1203,1501 894,1501 730,1665 U9.34@730,1850 ; U4.1@2591,1625 2596,1630 3075,1630 ; v1(2671.65,830) v1@2916.65,830 ; v1@2921.65,915 v1(2921.65,910) v1(2921.65,830) 2921.65,753.95 3160,515.6 3527.06,515.6 U6.1@3710,698.54 3720,708.54 4683.54,708.54 4802.48,827.48 4802.48,1178 ; U5.1@3170,1150 3347.23,1150 3509.23,1312 4670.49,1312 J4.2@4750.22,1232.27 4802.48,1180.01 4802.48,1178 ; U7.1@4265,160 4442.23,160 4572.23,290 v1(4755,290) 5110.5,290 5187,366.5 5187,1093 5102,1178 4802.48,1178 ; v1(4970,545) 5175,545 ; 5187,1088.58 5520,1088.58 ; J5.4@5456.69,706.81 5520,770.13 5520,1258.46 5266.73,1511.73 4793.27,1511.73 4675,1630 3075,1630 ; U9.34@730,1850 825,1945 2885,1945 3075,1755 3075,1630
  Bottom Layer w10: C24.1@737.98,1792.47 C24.1@740.45,1790 ; U3.18@1092.36,736.14 1092.36,666.14 C16.1@1103.5,655 ; U3.50@1230.16,1253.86 1230.16,1325.16 1239.4,1334.4 C15.1@1254.52,1334.4 1255,1334.88 v1(1255,1385) ; v1(4755,290) 4756.5,288.5 R4.2@4810,288.5 ; v1(4970,545) 4971.5,543.5 R7.2@5025,543.5 ; R2.2@5000,283.5 5053.5,283.5 v1(5055,285)
  Bottom Layer w30: U9.34@730,1850 730,1791.5 C24.1@733.5,1788
  other v1: 1000,505 1040,505 1075,505
+3P3V_OUT: C1.1 J3.2 U1.5 | length 234.4
  Bottom Layer w20: U1.5@4723,938.83 4723,979.24 4724.37,980.61 4724.37,984.36 4753.01,1013 4768,1013
  Bottom Layer w30: J3.2@4750.22,1132.27 4795,1087.49 C1.1@4795,1018
A0_DISP: U3.34 U9.38 | length 1232.8
  Bottom Layer w10: U9.38@330,1860 330,1430 696.1,1063.9 U3.34@981.14,1063.9
ADC_A0: C34.1 R10.2 U3.77 | length 993.5
  Top Layer w10: v1@1350,1015 1350,1254.67 1355,1259.67 1355,1260 1600,1505 v2(1665,1505)
  Bottom Layer w10: v1(1350,1010) 1374,1010 1434,950 1434,886 1452.95,867.05 U3.77@1498.86,867.05 ; C34.1@1676.38,1466.3 1665,1477.68 v2(1665,1505) 1665,1534.92 R10.2@1676.38,1546.3
ADC_A1: C35.1 R11.2 U3.78 | length 1414.3
  Top Layer w10: 1980,710 2220,950 v2(2220,1120)
  Top Layer w12: v1(1405,930) 1435,900 1580,900 1770,710 1980,710
  Bottom Layer w10: v1(1405,930) 1405,879 1436.64,847.36 U3.78@1498.86,847.36 ; C35.1@2219.06,1078.7 2220,1079.65 v2(2220,1120) 2220,1157.76 R11.2@2219.06,1158.7
ADC_A2: C36.1 R12.2 U3.79 | length 1186.4
  Top Layer w12: v1(1365,840) 1378.08,840 1643.08,575 2125,575 v2(2195,645)
  Bottom Layer w10: v1(1365,840) 1377.32,827.68 U3.79@1498.86,827.68
  Bottom Layer w12: C36.1@2195,606.85 v2(2195,645) R12.2@2195,685.55
ADC_A3: C37.1 R13.2 U3.80 | length 642.8
  Top Layer w12: v1(1270,810) 1270,755 v2(1475,550)
  Bottom Layer w10: v1(1270,810) 1272.01,807.99 U3.80@1498.86,807.99
  Bottom Layer w12: C37.1@1436,551.5 1473.5,551.5 v2(1475,550) R13.2@1503.62,550
AVCC: C17.1 C18.1 L3.2 U3.11 | length 83.7
  Bottom Layer w10: U3.11@1230.16,736.14 1230.16,661.22 C17.1@1236.38,655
